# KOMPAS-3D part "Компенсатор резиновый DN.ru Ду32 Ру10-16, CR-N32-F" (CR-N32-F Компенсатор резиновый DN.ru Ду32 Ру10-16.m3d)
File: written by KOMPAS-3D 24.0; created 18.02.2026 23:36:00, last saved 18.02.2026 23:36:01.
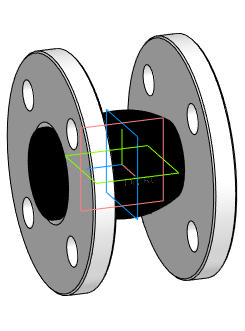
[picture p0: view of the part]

Document properties: Автор: DN.RU; Полное имя файла: D:\PROJECT CAD\DN.RU\...178(2)(ACTUALE). CR-N32-F Компенсатор резиновый DN.ru Ру10-16\CR-N32-F Компенсатор резиновый DN.ru Ру10-16\DN32\CR-N32-F Компенсатор резиновый DN.ru Ду32 Ру10-16.m3d

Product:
- Body: Твердое тело2  | qty 1
    Масса: 3.844501
- Part/product: Компенсатор резиновый DN.ru Ду32 Ру10-16  | designation CR-N32-F
    Масса: 3
    Раздел спецификации: Прочие изделия
    Комментарий: D140-02374
    Примечание: D140-02374
    additional columns: Типовые

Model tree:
1. Твердое тело2  (labels: Твердое тело2)

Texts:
  CR-N32-F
